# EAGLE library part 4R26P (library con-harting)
CONNECTOR
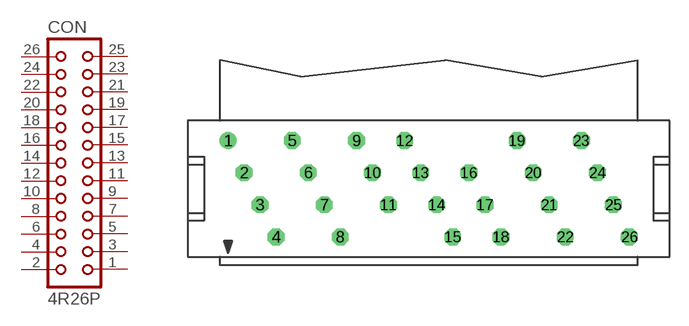
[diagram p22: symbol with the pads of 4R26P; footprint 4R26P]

Designator prefix CON

## 4R26P (OC_FARNELL: unknown; OC_NEWARK: unknown)  [4R26P]
1  1  pas
2  2  pas
3  3  pas
4  4  pas
5  5  pas
6  6  pas
7  7  pas
8  8  pas
9  9  pas
10  10  pas
11  11  pas
12  12  pas
13  13  pas
14  14  pas
15  15  pas
16  16  pas
17  17  pas
18  18  pas
19  19  pas
20  20  pas
21  21  pas
22  22  pas
23  23  pas
24  24  pas
25  25  pas
26  26  pas

## Footprint 4R26P (pad centres in mm)
CONNECTOR
drill 0.813 round: 1 -15.875,3.81
drill 0.813 octagon: 2 -14.605,1.27; 3 -13.335,-1.27; 4 -12.065,-3.81; 5 -10.795,3.81; 6 -9.525,1.27; 7 -8.255,-1.27; 8 -6.985,-3.81; 9 -5.715,3.81; 10 -4.445,1.27; 11 -3.175,-1.27; 12 -1.905,3.81; 13 -0.635,1.27; 14 0.635,-1.27; 15 1.905,-3.81; 16 3.175,1.27; 17 4.445,-1.27; 18 5.715,-3.81; 19 6.985,3.81; 20 8.255,1.27; 21 9.525,-1.27; 22 10.795,-3.81; 23 12.065,3.81; 24 13.335,1.27; 25 14.605,-1.27; 26 15.875,-3.81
